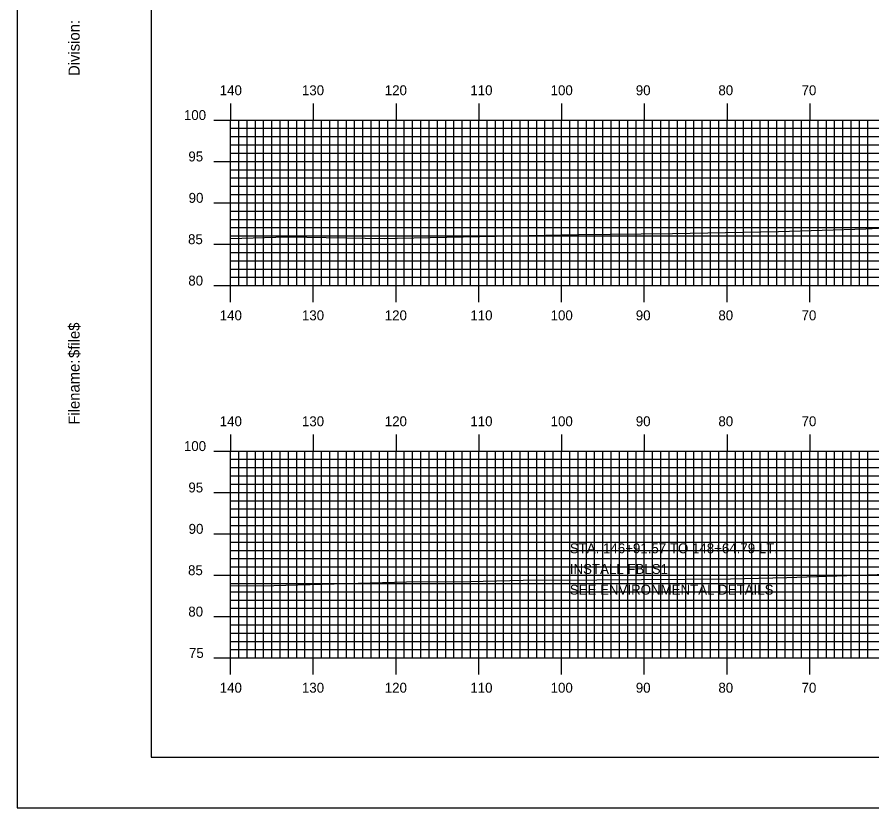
# Model space of a CAD drawing. Extents: x 1777925 to 1778268, y 442591 to 442811.
# Drawn here: x 1777925 to 1778028.3, y 442590.5 to 442686.1 of the extents above; entities that cross this region are included whole.
import ezdxf

# ---------------------------------------------------------------- set-up
doc = ezdxf.new("R2010")
doc.units = 0
for name, color, linetype in [('BORDER', 7, 'Continuous'), ('D_Text_Standard', 7, 'Continuous'), ('H_V ANNOTATION', 7, 'Continuous'), ('MAJOR', 7, 'Continuous'), ('MINOR', 7, 'Continuous'), ('PLOT BOUNDARY', 7, 'Continuous'), ('S_Roadway_Centerline', 7, 'Continuous')]:
    doc.layers.add(name, color=color, linetype=linetype)

msp = doc.modelspace()

# ---------------------------------------------------------------- linework, layer by layer
at = {"layer": 'BORDER'}
msp.add_lwpolyline([(1777941.19, 442596.67), (1778261.19, 442596.67), (1778261.19, 442806.67), (1777941.19, 442806.67)], close=True, dxfattribs=at)
at = {"layer": 'MAJOR'}
for p, q in [((1777950.79, 442675.67), (1777950.79, 442673.67)), ((1777960.79, 442675.67), (1777960.79, 442673.67)), ((1777970.79, 442675.67), (1777970.79, 442673.67)), ((1777980.79, 442675.67), (1777980.79, 442673.67)), ((1777990.79, 442675.67), (1777990.79, 442673.67)), ((1778000.79, 442675.67), (1778000.79, 442673.67)), ((1778010.79, 442675.67), (1778010.79, 442673.67)), ((1778020.79, 442675.67), (1778020.79, 442673.67)), ((1777948.79, 442673.67), (1777950.79, 442673.67)), ((1777950.79, 442673.67), (1778230.79, 442673.67)), ((1777950.79, 442653.67), (1777950.79, 442673.67)), ((1777950.79, 442653.67), (1777950.79, 442673.67)), ((1777950.79, 442673.67), (1778230.79, 442673.67)), ((1777960.79, 442653.67), (1777960.79, 442673.67)), ((1777970.79, 442653.67), (1777970.79, 442673.67)), ((1777980.79, 442653.67), (1777980.79, 442673.67)), ((1777990.79, 442653.67), (1777990.79, 442673.67)), ((1778000.79, 442653.67), (1778000.79, 442673.67)), ((1778010.79, 442653.67), (1778010.79, 442673.67)), ((1778020.79, 442653.67), (1778020.79, 442673.67)), ((1777948.79, 442668.67), (1777950.79, 442668.67)), ((1777950.79, 442668.67), (1778230.79, 442668.67)), ((1777948.79, 442663.67), (1777950.79, 442663.67)), ((1777950.79, 442663.67), (1778230.79, 442663.67)), ((1777948.79, 442658.67), (1777950.79, 442658.67)), ((1777950.79, 442658.67), (1778230.79, 442658.67)), ((1777948.79, 442653.67), (1777950.79, 442653.67)), ((1777950.79, 442653.67), (1778230.79, 442653.67)), ((1777950.79, 442653.67), (1778230.79, 442653.67)), ((1777950.79, 442651.66), (1777950.79, 442653.67)), ((1777960.79, 442651.66), (1777960.79, 442653.67)), ((1777970.79, 442651.66), (1777970.79, 442653.67)), ((1777980.79, 442651.66), (1777980.79, 442653.67)), ((1777990.79, 442651.66), (1777990.79, 442653.67)), ((1778000.79, 442651.66), (1778000.79, 442653.67)), ((1778010.79, 442651.66), (1778010.79, 442653.67)), ((1778020.79, 442651.66), (1778020.79, 442653.67)), ((1777950.79, 442635.67), (1777950.79, 442633.67)), ((1777960.79, 442635.67), (1777960.79, 442633.67)), ((1777970.79, 442635.67), (1777970.79, 442633.67)), ((1777980.79, 442635.67), (1777980.79, 442633.67)), ((1777990.79, 442635.67), (1777990.79, 442633.67)), ((1778000.79, 442635.67), (1778000.79, 442633.67)), ((1778010.79, 442635.67), (1778010.79, 442633.67)), ((1778020.79, 442635.67), (1778020.79, 442633.67)), ((1777948.79, 442633.67), (1777950.79, 442633.67)), ((1777950.79, 442633.67), (1778230.79, 442633.67)), ((1777950.79, 442608.67), (1777950.79, 442633.67)), ((1777950.79, 442608.67), (1777950.79, 442633.67)), ((1777950.79, 442633.67), (1778230.79, 442633.67)), ((1777960.79, 442608.67), (1777960.79, 442633.67)), ((1777970.79, 442608.67), (1777970.79, 442633.67)), ((1777980.79, 442608.67), (1777980.79, 442633.67)), ((1777990.79, 442608.67), (1777990.79, 442633.67)), ((1778000.79, 442608.67), (1778000.79, 442633.67)), ((1778010.79, 442608.67), (1778010.79, 442633.67)), ((1778020.79, 442608.67), (1778020.79, 442633.67)), ((1777948.79, 442628.67), (1777950.79, 442628.67)), ((1777950.79, 442628.67), (1778230.79, 442628.67)), ((1777948.79, 442623.67), (1777950.79, 442623.67)), ((1777950.79, 442623.67), (1778230.79, 442623.67)), ((1777948.79, 442618.67), (1777950.79, 442618.67)), ((1777950.79, 442618.67), (1778230.79, 442618.67)), ((1777948.79, 442613.67), (1777950.79, 442613.67)), ((1777950.79, 442613.67), (1778230.79, 442613.67)), ((1777948.79, 442608.67), (1777950.79, 442608.67)), ((1777950.79, 442608.67), (1778230.79, 442608.67)), ((1777950.79, 442608.67), (1778230.79, 442608.67)), ((1777950.79, 442606.66), (1777950.79, 442608.67)), ((1777960.79, 442606.66), (1777960.79, 442608.67)), ((1777970.79, 442606.66), (1777970.79, 442608.67)), ((1777980.79, 442606.66), (1777980.79, 442608.67)), ((1777990.79, 442606.66), (1777990.79, 442608.67)), ((1778000.79, 442606.66), (1778000.79, 442608.67)), ((1778010.79, 442606.66), (1778010.79, 442608.67)), ((1778020.79, 442606.66), (1778020.79, 442608.67))]:
    msp.add_line(p, q, dxfattribs=at)
at = {"layer": 'MINOR'}
for p, q in [((1777951.79, 442653.67), (1777951.79, 442673.67)), ((1777952.79, 442653.67), (1777952.79, 442673.67)), ((1777953.79, 442653.67), (1777953.79, 442673.67)), ((1777954.79, 442653.67), (1777954.79, 442673.67)), ((1777955.79, 442653.67), (1777955.79, 442673.67)), ((1777956.79, 442653.67), (1777956.79, 442673.67)), ((1777957.79, 442653.67), (1777957.79, 442673.67)), ((1777958.79, 442653.67), (1777958.79, 442673.67)), ((1777959.79, 442653.67), (1777959.79, 442673.67)), ((1777961.79, 442653.67), (1777961.79, 442673.67)), ((1777962.79, 442653.67), (1777962.79, 442673.67)), ((1777963.79, 442653.67), (1777963.79, 442673.67)), ((1777964.79, 442653.67), (1777964.79, 442673.67)), ((1777965.79, 442653.67), (1777965.79, 442673.67)), ((1777966.79, 442653.67), (1777966.79, 442673.67)), ((1777967.79, 442653.67), (1777967.79, 442673.67)), ((1777968.79, 442653.67), (1777968.79, 442673.67)), ((1777969.79, 442653.67), (1777969.79, 442673.67)), ((1777971.79, 442653.67), (1777971.79, 442673.67)), ((1777972.79, 442653.67), (1777972.79, 442673.67)), ((1777973.79, 442653.67), (1777973.79, 442673.67)), ((1777974.79, 442653.67), (1777974.79, 442673.67)), ((1777975.79, 442653.67), (1777975.79, 442673.67)), ((1777976.79, 442653.67), (1777976.79, 442673.67)), ((1777977.79, 442653.67), (1777977.79, 442673.67)), ((1777978.79, 442653.67), (1777978.79, 442673.67)), ((1777979.79, 442653.67), (1777979.79, 442673.67)), ((1777981.79, 442653.67), (1777981.79, 442673.67)), ((1777982.79, 442653.67), (1777982.79, 442673.67)), ((1777983.79, 442653.67), (1777983.79, 442673.67)), ((1777984.79, 442653.67), (1777984.79, 442673.67)), ((1777985.79, 442653.67), (1777985.79, 442673.67)), ((1777986.79, 442653.67), (1777986.79, 442673.67)), ((1777987.79, 442653.67), (1777987.79, 442673.67)), ((1777988.79, 442653.67), (1777988.79, 442673.67)), ((1777989.79, 442653.67), (1777989.79, 442673.67)), ((1777991.79, 442653.67), (1777991.79, 442673.67)), ((1777992.79, 442653.67), (1777992.79, 442673.67)), ((1777993.79, 442653.67), (1777993.79, 442673.67)), ((1777994.79, 442653.67), (1777994.79, 442673.67)), ((1777995.79, 442653.67), (1777995.79, 442673.67)), ((1777996.79, 442653.67), (1777996.79, 442673.67)), ((1777997.79, 442653.67), (1777997.79, 442673.67)), ((1777998.79, 442653.67), (1777998.79, 442673.67)), ((1777999.79, 442653.67), (1777999.79, 442673.67)), ((1778001.79, 442653.67), (1778001.79, 442673.67)), ((1778002.79, 442653.67), (1778002.79, 442673.67)), ((1778003.79, 442653.67), (1778003.79, 442673.67)), ((1778004.79, 442653.67), (1778004.79, 442673.67)), ((1778005.79, 442653.67), (1778005.79, 442673.67)), ((1778006.79, 442653.67), (1778006.79, 442673.67)), ((1778007.79, 442653.67), (1778007.79, 442673.67)), ((1778008.79, 442653.67), (1778008.79, 442673.67)), ((1778009.79, 442653.67), (1778009.79, 442673.67)), ((1778011.79, 442653.67), (1778011.79, 442673.67)), ((1778012.79, 442653.67), (1778012.79, 442673.67)), ((1778013.79, 442653.67), (1778013.79, 442673.67)), ((1778014.79, 442653.67), (1778014.79, 442673.67)), ((1778015.79, 442653.67), (1778015.79, 442673.67)), ((1778016.79, 442653.67), (1778016.79, 442673.67)), ((1778017.79, 442653.67), (1778017.79, 442673.67)), ((1778018.79, 442653.67), (1778018.79, 442673.67)), ((1778019.79, 442653.67), (1778019.79, 442673.67)), ((1778021.79, 442653.67), (1778021.79, 442673.67)), ((1778022.79, 442653.67), (1778022.79, 442673.67)), ((1778023.79, 442653.67), (1778023.79, 442673.67)), ((1778024.79, 442653.67), (1778024.79, 442673.67)), ((1778025.79, 442653.67), (1778025.79, 442673.67)), ((1778026.79, 442653.67), (1778026.79, 442673.67)), ((1778027.79, 442653.67), (1778027.79, 442673.67)), ((1777950.79, 442672.67), (1778230.79, 442672.67)), ((1777950.79, 442672.67), (1777952.79, 442672.67)), ((1777950.79, 442671.67), (1778230.79, 442671.67)), ((1777950.79, 442671.67), (1777952.79, 442671.67)), ((1777950.79, 442670.67), (1778230.79, 442670.67)), ((1777950.79, 442670.67), (1777952.79, 442670.67)), ((1777950.79, 442669.67), (1778230.79, 442669.67)), ((1777950.79, 442669.67), (1777952.79, 442669.67)), ((1777950.79, 442667.67), (1778230.79, 442667.67)), ((1777950.79, 442667.67), (1777952.79, 442667.67)), ((1777950.79, 442666.67), (1778230.79, 442666.67)), ((1777950.79, 442666.67), (1777952.79, 442666.67)), ((1777950.79, 442665.67), (1778230.79, 442665.67)), ((1777950.79, 442665.67), (1777952.79, 442665.67)), ((1777950.79, 442664.67), (1778230.79, 442664.67)), ((1777950.79, 442664.67), (1777952.79, 442664.67)), ((1777950.79, 442662.67), (1778230.79, 442662.67)), ((1777950.79, 442662.67), (1777952.79, 442662.67)), ((1777950.79, 442661.67), (1778230.79, 442661.67)), ((1777950.79, 442661.67), (1777952.79, 442661.67)), ((1777950.79, 442660.67), (1778230.79, 442660.67)), ((1777950.79, 442660.67), (1777952.79, 442660.67)), ((1777950.79, 442659.67), (1778230.79, 442659.67)), ((1777950.79, 442659.67), (1777952.79, 442659.67)), ((1777950.79, 442657.67), (1778230.79, 442657.67)), ((1777950.79, 442657.67), (1777952.79, 442657.67)), ((1777950.79, 442656.67), (1778230.79, 442656.67)), ((1777950.79, 442656.67), (1777952.79, 442656.67)), ((1777950.79, 442655.67), (1778230.79, 442655.67)), ((1777950.79, 442655.67), (1777952.79, 442655.67)), ((1777950.79, 442654.67), (1778230.79, 442654.67)), ((1777950.79, 442654.67), (1777952.79, 442654.67)), ((1777951.79, 442608.67), (1777951.79, 442633.67)), ((1777952.79, 442608.67), (1777952.79, 442633.67)), ((1777953.79, 442608.67), (1777953.79, 442633.67)), ((1777954.79, 442608.67), (1777954.79, 442633.67)), ((1777955.79, 442608.67), (1777955.79, 442633.67)), ((1777956.79, 442608.67), (1777956.79, 442633.67)), ((1777957.79, 442608.67), (1777957.79, 442633.67)), ((1777958.79, 442608.67), (1777958.79, 442633.67)), ((1777959.79, 442608.67), (1777959.79, 442633.67)), ((1777961.79, 442608.67), (1777961.79, 442633.67)), ((1777962.79, 442608.67), (1777962.79, 442633.67)), ((1777963.79, 442608.67), (1777963.79, 442633.67)), ((1777964.79, 442608.67), (1777964.79, 442633.67)), ((1777965.79, 442608.67), (1777965.79, 442633.67)), ((1777966.79, 442608.67), (1777966.79, 442633.67)), ((1777967.79, 442608.67), (1777967.79, 442633.67)), ((1777968.79, 442608.67), (1777968.79, 442633.67)), ((1777969.79, 442608.67), (1777969.79, 442633.67)), ((1777971.79, 442608.67), (1777971.79, 442633.67)), ((1777972.79, 442608.67), (1777972.79, 442633.67)), ((1777973.79, 442608.67), (1777973.79, 442633.67)), ((1777974.79, 442608.67), (1777974.79, 442633.67)), ((1777975.79, 442608.67), (1777975.79, 442633.67)), ((1777976.79, 442608.67), (1777976.79, 442633.67)), ((1777977.79, 442608.67), (1777977.79, 442633.67)), ((1777978.79, 442608.67), (1777978.79, 442633.67)), ((1777979.79, 442608.67), (1777979.79, 442633.67)), ((1777981.79, 442608.67), (1777981.79, 442633.67)), ((1777982.79, 442608.67), (1777982.79, 442633.67)), ((1777983.79, 442608.67), (1777983.79, 442633.67)), ((1777984.79, 442608.67), (1777984.79, 442633.67)), ((1777985.79, 442608.67), (1777985.79, 442633.67)), ((1777986.79, 442608.67), (1777986.79, 442633.67)), ((1777987.79, 442608.67), (1777987.79, 442633.67)), ((1777988.79, 442608.67), (1777988.79, 442633.67)), ((1777989.79, 442608.67), (1777989.79, 442633.67)), ((1777991.79, 442608.67), (1777991.79, 442633.67)), ((1777992.79, 442608.67), (1777992.79, 442633.67)), ((1777993.79, 442608.67), (1777993.79, 442633.67)), ((1777994.79, 442608.67), (1777994.79, 442633.67)), ((1777995.79, 442608.67), (1777995.79, 442633.67)), ((1777996.79, 442608.67), (1777996.79, 442633.67)), ((1777997.79, 442608.67), (1777997.79, 442633.67)), ((1777998.79, 442608.67), (1777998.79, 442633.67)), ((1777999.79, 442608.67), (1777999.79, 442633.67)), ((1778001.79, 442608.67), (1778001.79, 442633.67)), ((1778002.79, 442608.67), (1778002.79, 442633.67)), ((1778003.79, 442608.67), (1778003.79, 442633.67)), ((1778004.79, 442608.67), (1778004.79, 442633.67)), ((1778005.79, 442608.67), (1778005.79, 442633.67)), ((1778006.79, 442608.67), (1778006.79, 442633.67)), ((1778007.79, 442608.67), (1778007.79, 442633.67)), ((1778008.79, 442608.67), (1778008.79, 442633.67)), ((1778009.79, 442608.67), (1778009.79, 442633.67)), ((1778011.79, 442608.67), (1778011.79, 442633.67)), ((1778012.79, 442608.67), (1778012.79, 442633.67)), ((1778013.79, 442608.67), (1778013.79, 442633.67)), ((1778014.79, 442608.67), (1778014.79, 442633.67)), ((1778015.79, 442608.67), (1778015.79, 442633.67)), ((1778016.79, 442608.67), (1778016.79, 442633.67)), ((1778017.79, 442608.67), (1778017.79, 442633.67)), ((1778018.79, 442608.67), (1778018.79, 442633.67)), ((1778019.79, 442608.67), (1778019.79, 442633.67)), ((1778021.79, 442608.67), (1778021.79, 442633.67)), ((1778022.79, 442608.67), (1778022.79, 442633.67)), ((1778023.79, 442608.67), (1778023.79, 442633.67)), ((1778024.79, 442608.67), (1778024.79, 442633.67)), ((1778025.79, 442608.67), (1778025.79, 442633.67)), ((1778026.79, 442608.67), (1778026.79, 442633.67)), ((1778027.79, 442608.67), (1778027.79, 442633.67)), ((1777950.79, 442632.67), (1778230.79, 442632.67)), ((1777950.79, 442632.67), (1777952.79, 442632.67)), ((1777950.79, 442631.67), (1778230.79, 442631.67)), ((1777950.79, 442631.67), (1777952.79, 442631.67)), ((1777950.79, 442630.67), (1778230.79, 442630.67)), ((1777950.79, 442630.67), (1777952.79, 442630.67)), ((1777950.79, 442629.67), (1778230.79, 442629.67)), ((1777950.79, 442629.67), (1777952.79, 442629.67)), ((1777950.79, 442627.67), (1778230.79, 442627.67)), ((1777950.79, 442627.67), (1777952.79, 442627.67)), ((1777950.79, 442626.67), (1778230.79, 442626.67)), ((1777950.79, 442626.67), (1777952.79, 442626.67)), ((1777950.79, 442625.67), (1778230.79, 442625.67)), ((1777950.79, 442625.67), (1777952.79, 442625.67)), ((1777950.79, 442624.67), (1778230.79, 442624.67)), ((1777950.79, 442624.67), (1777952.79, 442624.67)), ((1777950.79, 442622.67), (1778230.79, 442622.67)), ((1777950.79, 442622.67), (1777952.79, 442622.67)), ((1777950.79, 442621.67), (1778230.79, 442621.67)), ((1777950.79, 442621.67), (1777952.79, 442621.67)), ((1777950.79, 442620.67), (1778230.79, 442620.67)), ((1777950.79, 442620.67), (1777952.79, 442620.67)), ((1777950.79, 442619.67), (1778230.79, 442619.67)), ((1777950.79, 442619.67), (1777952.79, 442619.67)), ((1777950.79, 442617.67), (1778230.79, 442617.67)), ((1777950.79, 442617.67), (1777952.79, 442617.67)), ((1777950.79, 442616.67), (1778230.79, 442616.67)), ((1777950.79, 442616.67), (1777952.79, 442616.67)), ((1777950.79, 442615.67), (1778230.79, 442615.67)), ((1777950.79, 442615.67), (1777952.79, 442615.67)), ((1777950.79, 442614.67), (1778230.79, 442614.67)), ((1777950.79, 442614.67), (1777952.79, 442614.67)), ((1777950.79, 442612.67), (1778230.79, 442612.67)), ((1777950.79, 442612.67), (1777952.79, 442612.67)), ((1777950.79, 442611.67), (1778230.79, 442611.67)), ((1777950.79, 442611.67), (1777952.79, 442611.67)), ((1777950.79, 442610.67), (1778230.79, 442610.67)), ((1777950.79, 442610.67), (1777952.79, 442610.67)), ((1777950.79, 442609.67), (1778230.79, 442609.67)), ((1777950.79, 442609.67), (1777952.79, 442609.67))]:
    msp.add_line(p, q, dxfattribs=at)
at = {"layer": 'PLOT BOUNDARY'}
msp.add_lwpolyline([(1777925, 442590.55), (1778265, 442590.55), (1778265, 442810.55), (1777925, 442810.55)], close=True, dxfattribs=at)
at = {"layer": 'S_Roadway_Centerline'}
for points in [[(1777950.79, 442659.34), (1777957.64, 442659.57), (1777969.44, 442659.35), (1777970.92, 442659.38), (1777992.89, 442659.86), (1778004.18, 442659.95), (1778017.02, 442660.19), (1778027.55, 442660.53), (1778038.13, 442661.08), (1778040.82, 442661.18), (1778050.83, 442661.18), (1778061.02, 442661.22), (1778063.33, 442661.29), (1778065.36, 442661.25), (1778083.87, 442661.7), (1778097.82, 442662.03), (1778107.18, 442661.91), (1778109.11, 442661.93), (1778111.22, 442662.05), (1778128.39, 442662.84), (1778134.18, 442662.79)], [(1777950.79, 442617.39), (1777956.02, 442617.41), (1777972.06, 442617.85), (1777979.69, 442617.9), (1777987.77, 442618.09), (1777991.69, 442618.08), (1777995.06, 442618.12), (1778011.22, 442618.22), (1778018.03, 442618.39), (1778036.18, 442618.99), (1778037.81, 442619.08), (1778039.54, 442619.14), (1778058.95, 442619.76), (1778062.93, 442619.75), (1778072.12, 442620.01), (1778083.21, 442620.44), (1778085.44, 442620.54), (1778086.47, 442620.6), (1778107.62, 442620.45), (1778108.33, 442620.46), (1778129.19, 442620.76), (1778131.69, 442620.77), (1778142.05, 442621.16)]]:
    msp.add_lwpolyline(points, dxfattribs=at)

# ---------------------------------------------------------------- texts
at = {"layer": 'BORDER'}
for s, p in [('Division:', (1777932.56, 442679)), ('$file$', (1777932.56, 442644.92)), ('Filename:', (1777932.56, 442636.86))]:
    msp.add_text(s, height=1.339, rotation=90, dxfattribs=at).set_placement(p)
at = {"layer": 'D_Text_Standard'}
for s, p in [('STA. 146+91.57 TO 148+64.79 LT.', (1777991.79, 442621.32)), ('INSTALL FBLS1', (1777991.79, 442618.82)), ('SEE ENVIRONMENTAL DETAILS', (1777991.79, 442616.32))]:
    msp.add_text(s, height=1.2, dxfattribs=at).set_placement(p)
at = {"layer": 'H_V ANNOTATION'}
for s, p in [('140', (1777949.49, 442676.67)), ('130', (1777959.42, 442676.67)), ('120', (1777969.43, 442676.67)), ('110', (1777979.77, 442676.67)), ('100', (1777989.47, 442676.67)), ('90', (1777999.76, 442676.67)), ('80', (1778009.74, 442676.67)), ('70', (1778019.79, 442676.67)), ('100', (1777945.16, 442673.67)), ('95', (1777945.7, 442668.67)), ('90', (1777945.73, 442663.67)), ('85', (1777945.66, 442658.67)), ('80', (1777945.69, 442653.67)), ('140', (1777949.49, 442649.47)), ('130', (1777959.42, 442649.47)), ('120', (1777969.43, 442649.47)), ('110', (1777979.77, 442649.47)), ('100', (1777989.47, 442649.47)), ('90', (1777999.76, 442649.47)), ('80', (1778009.74, 442649.47)), ('70', (1778019.79, 442649.47)), ('140', (1777949.49, 442636.67)), ('130', (1777959.42, 442636.67)), ('120', (1777969.43, 442636.67)), ('110', (1777979.77, 442636.67)), ('100', (1777989.47, 442636.67)), ('90', (1777999.76, 442636.67)), ('80', (1778009.74, 442636.67)), ('70', (1778019.79, 442636.67)), ('100', (1777945.16, 442633.67)), ('95', (1777945.7, 442628.67)), ('90', (1777945.73, 442623.67)), ('85', (1777945.66, 442618.67)), ('80', (1777945.69, 442613.67)), ('75', (1777945.77, 442608.67)), ('140', (1777949.49, 442604.47)), ('130', (1777959.42, 442604.47)), ('120', (1777969.43, 442604.47)), ('110', (1777979.77, 442604.47)), ('100', (1777989.47, 442604.47)), ('90', (1777999.76, 442604.47)), ('80', (1778009.74, 442604.47)), ('70', (1778019.79, 442604.47))]:
    msp.add_text(s, height=1.2, dxfattribs=at).set_placement(p)
at = {"layer": 'MAJOR'}
for p in [(1777950.78, 442653.67), (1777950.78, 442608.67)]:
    msp.add_text('-', height=0.012, dxfattribs=at).set_placement(p)

doc.saveas('drawing.dxf')
